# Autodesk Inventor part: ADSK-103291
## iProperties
Shininess: 0.0
Created: 2000-04
Part Number: ADSK-103291
Document SubType Name: Modeling
Stock Number: ADSK-103291
Density: 1 g/cm^3
Density: 0.0
Volumn: 0.0
Area: 0.0
PropertySet Name: Model Information
Control State: 0
Checked Out: False
Master: False
Author: gao
